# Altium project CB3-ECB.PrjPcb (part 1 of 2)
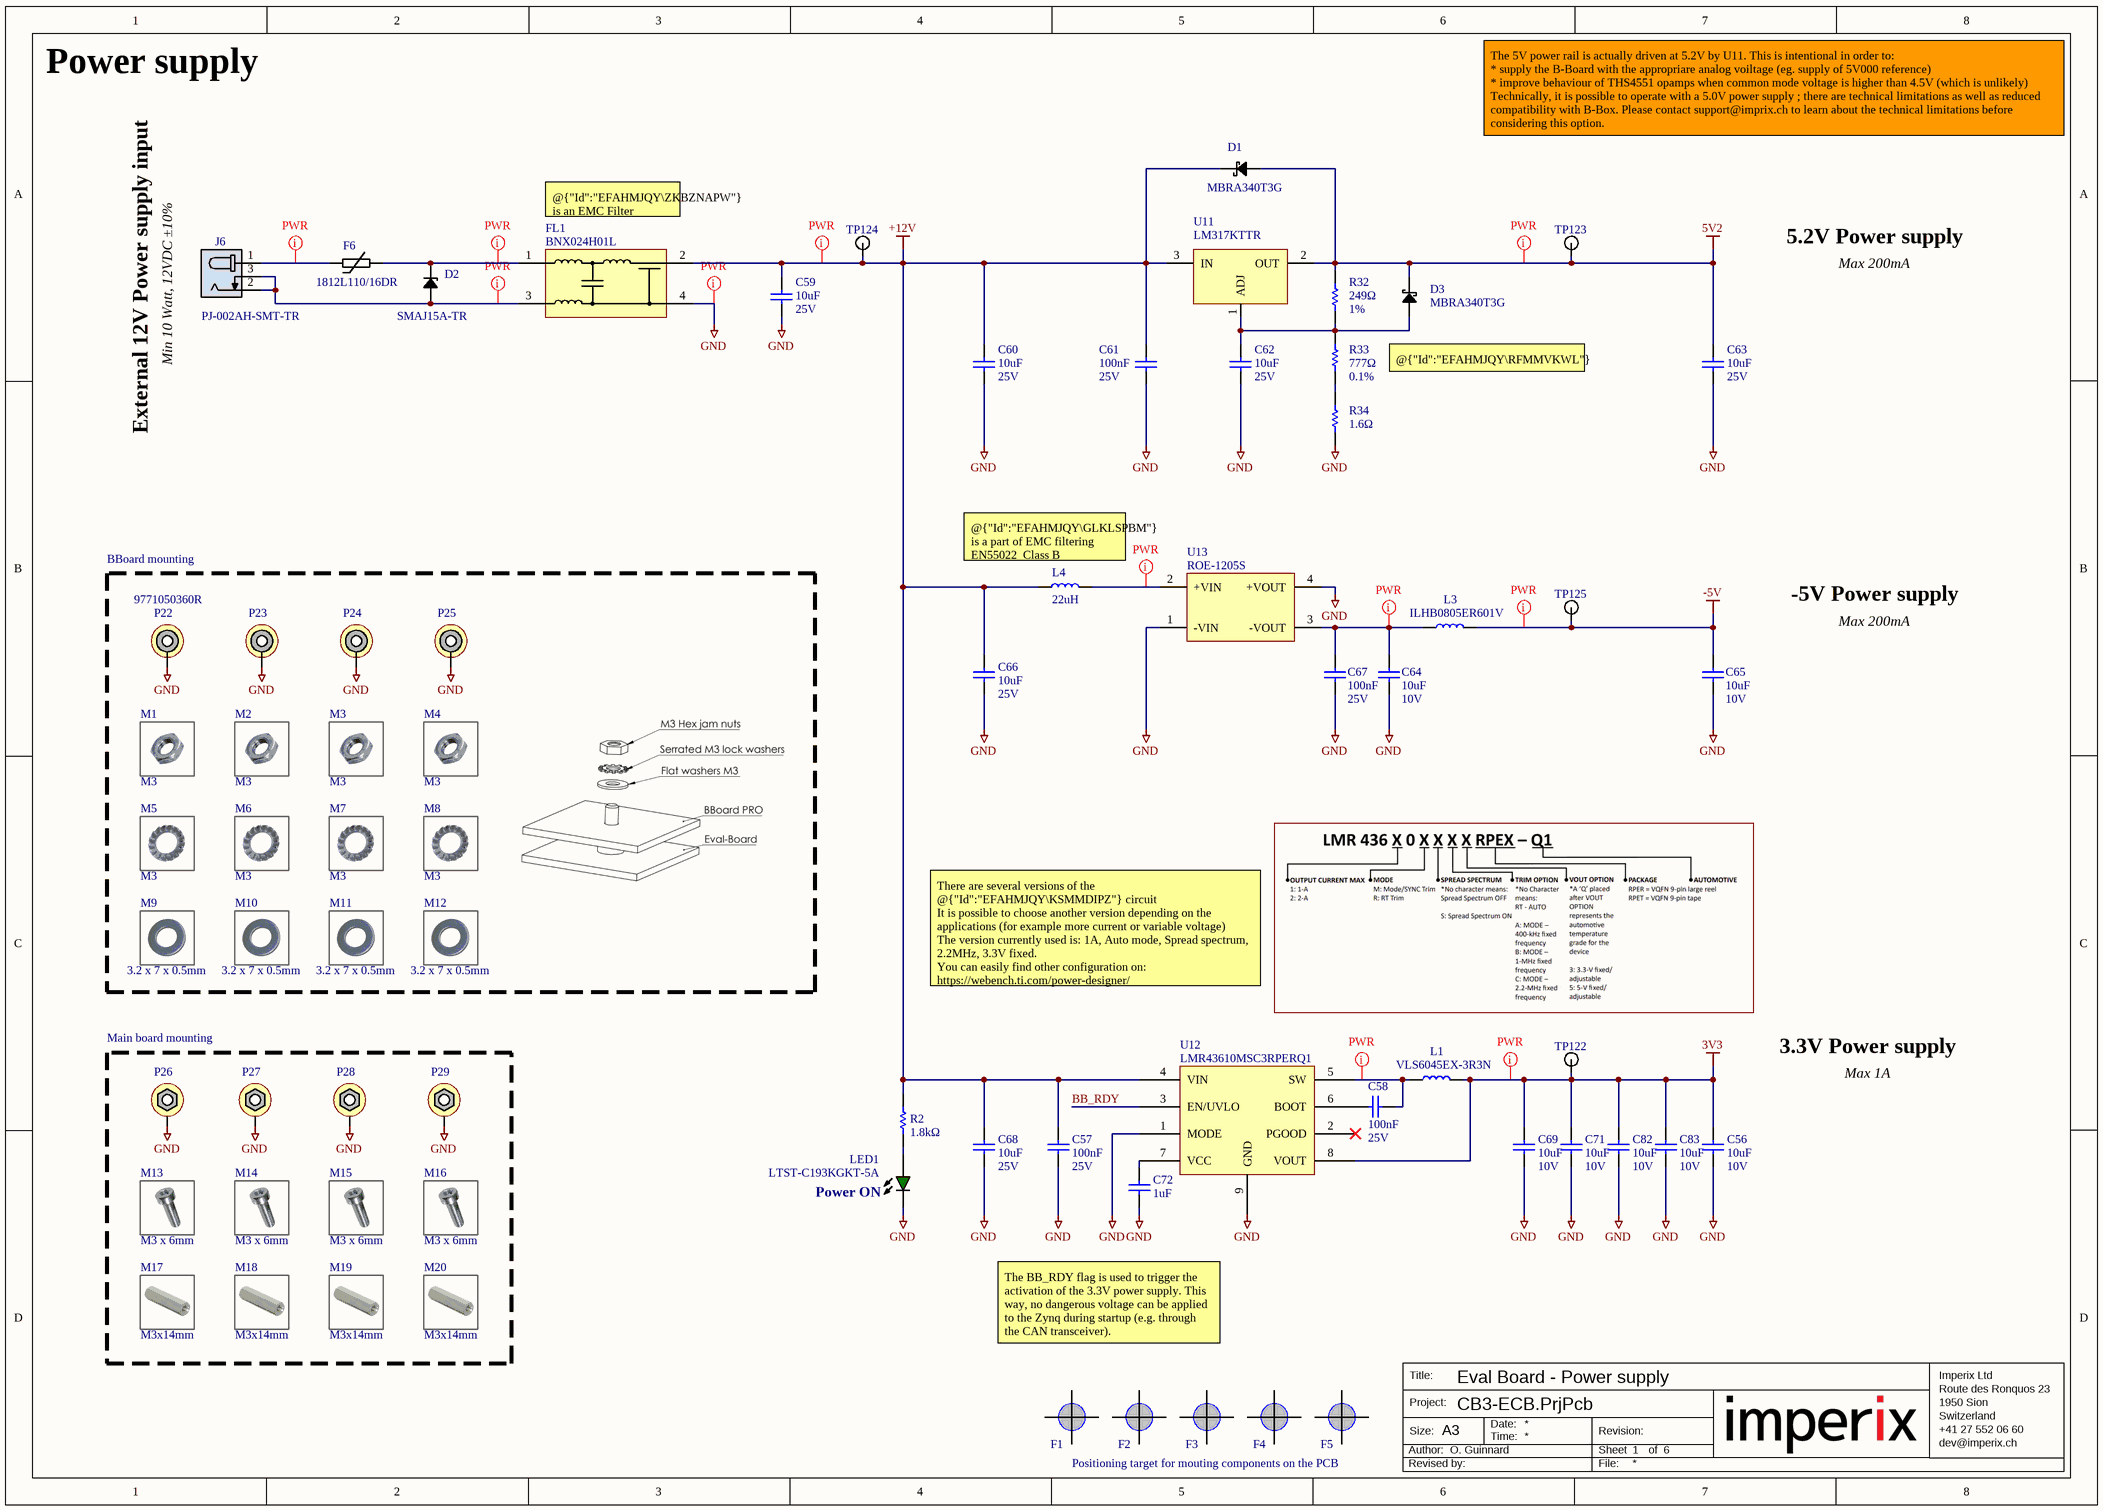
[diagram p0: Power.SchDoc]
ApprovedName: Nicolas Cherix; RevisionLetter: C; RevisionNumber: 1
6 sheets, 383 parts. Net scope: global (net labels, ports and power ports of the same name join across sheets).
Board files: CB3-ECB_PCB.PcbDoc, CB3_ECB_PCB_Pannelized.PcbDoc
Sheets:
  Power.SchDoc
  DAC.SchDoc
  ADC.SchDoc
  BBoard-JX1.SchDoc
  BBoard-JX2.SchDoc
  Test points.SchDoc

## Sheet Power.SchDoc: Eval Board - Power supply
size A3; ApprovedBy: Nicolas Cherix; Author: O. Guinnard; Organization: imperix Ltd; Address1: Rue de l'Industrie 10; Address2: 1950 Sion; Address3: Switzerland; Address4: +41 27 552 06 60; Revision: C1; SheetNumber: 1; SheetTotal: 6

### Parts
C56  value 10uF  Voltage Rating (DC): 10V  [CAPC1608L(0603)]  (hidden comment: CAP-10UF-10V-X5R-0603-10%)
C57  value 100nF  Voltage Rating (DC): 25V  [CAPC1005L(0402)]  (hidden comment: CAP-100NF-25V-X7R-0402-10%)
C58  value 100nF  Voltage Rating (DC): 25V  [CAPC1005L(0402)]  (hidden comment: CAP-100NF-25V-X7R-0402-10%)
C59  value 10uF  Voltage Rating (DC): 25V  [CAPC3216L(1206)]  (hidden comment: CAP-10UF-25V-X5R-1206-10%)
C60  value 10uF  Voltage Rating (DC): 25V  [CAPC3216L(1206)]  (hidden comment: CAP-10UF-25V-X5R-1206-10%)
C61  value 100nF  Voltage Rating (DC): 25V  [CAPC1005L(0402)]  (hidden comment: CAP-100NF-25V-X7R-0402-10%)
C62  value 10uF  Voltage Rating (DC): 25V  [CAPC3216L(1206)]  (hidden comment: CAP-10UF-25V-X5R-1206-10%)
C63  value 10uF  Voltage Rating (DC): 25V  [CAPC3216L(1206)]  (hidden comment: CAP-10UF-25V-X5R-1206-10%)
C64  value 10uF  Voltage Rating (DC): 10V  [CAPC1608L(0603)]  (hidden comment: CAP-10UF-10V-X5R-0603-10%)
C65  value 10uF  Voltage Rating (DC): 10V  [CAPC1608L(0603)]  (hidden comment: CAP-10UF-10V-X5R-0603-10%)
C66  value 10uF  Voltage Rating (DC): 25V  [CAPC3216L(1206)]  (hidden comment: CAP-10UF-25V-X5R-1206-10%)
C67  value 100nF  Voltage Rating (DC): 25V  [CAPC1005L(0402)]  (hidden comment: CAP-100NF-25V-X7R-0402-10%)
C68  value 10uF  Voltage Rating (DC): 25V  [CAPC3216L(1206)]  (hidden comment: CAP-10UF-25V-X5R-1206-10%)
C69  value 10uF  Voltage Rating (DC): 10V  [CAPC1608L(0603)]  (hidden comment: CAP-10UF-10V-X5R-0603-10%)
C71  value 10uF  Voltage Rating (DC): 10V  [CAPC1608L(0603)]  (hidden comment: CAP-10UF-10V-X5R-0603-10%)
C72  value 1uF  [CAPC1005L(0402)]  (hidden comment: CAP-1UF-6.3V-X5R-0402-5%)
C82  value 10uF  Voltage Rating (DC): 10V  [CAPC1608L(0603)]  (hidden comment: CAP-10UF-10V-X5R-0603-10%)
C83  value 10uF  Voltage Rating (DC): 10V  [CAPC1608L(0603)]  (hidden comment: CAP-10UF-10V-X5R-0603-10%)
D1  MBRA340T3G  [DO-214AC]
D2  SMAJ15A-TR  [DO-214AC]
D3  MBRA340T3G  [DO-214AC]
F1  Fiducial  [Fiducial050]  (value not drawn)  (no BOM)
F2  Fiducial  [Fiducial050]  (value not drawn)  (no BOM)
F3  Fiducial  [Fiducial050]  (value not drawn)  (no BOM)
F4  Fiducial  [Fiducial050]  (value not drawn)  (no BOM)
F5  Fiducial  [Fiducial050]  (value not drawn)  (no BOM)
F6  1812L110/16DR  [PTC Fuse(1812)]
FL1  BNX024H01L  [FP-BNX02-MFG]
J6  PJ-002AH-SMT-TR  [PJ-002AH-SMT-TR]
L1  VLS6045EX-3R3N  [VLS6045EX]
L3  ILHB0805ER601V  [RESC2012L(0805)]
L4  value 22uH  [Inductor 8400 Serie]  (hidden comment: 84223C)
LED1  LTST-C193KGKT-5A  [LED0603_GREEN]
M1  value M3  (hidden comment: 1090615)  (mechanical)
M2  value M3  (hidden comment: 1090615)  (mechanical)
M3  value M3  (hidden comment: 1090615)  (mechanical)
M4  value M3  (hidden comment: 1090615)  (mechanical)
M5  value M3  (hidden comment: 1278037)  (mechanical)
M6  value M3  (hidden comment: 1278037)  (mechanical)
M7  value M3  (hidden comment: 1278037)  (mechanical)
M8  value M3  (hidden comment: 1278037)  (mechanical)
M9  value 3.2 x 7 x 0.5mm  (hidden comment: 1887467)  (mechanical)
M10  value 3.2 x 7 x 0.5mm  (hidden comment: 1887467)  (mechanical)
M11  value 3.2 x 7 x 0.5mm  (hidden comment: 1887467)  (mechanical)
M12  value 3.2 x 7 x 0.5mm  (hidden comment: 1887467)  (mechanical)
M13  value M3 x 6mm  (hidden comment: 1145924)  (mechanical)
M14  value M3 x 6mm  (hidden comment: 1145924)  (mechanical)
M15  value M3 x 6mm  (hidden comment: 1145924)  (mechanical)
M16  value M3 x 6mm  (hidden comment: 1145924)  (mechanical)
M17  value M3x14mm  (hidden comment: 1382748)  (mechanical)
M18  value M3x14mm  (hidden comment: 1382748)  (mechanical)
M19  value M3x14mm  (hidden comment: 1382748)  (mechanical)
M20  value M3x14mm  (hidden comment: 1382748)  (mechanical)
P22  9771050360R  [9771050360R]
P23  9771050360R  [9771050360R]  (value not drawn)
P24  9771050360R  [9771050360R]  (value not drawn)
P25  9771050360R  [9771050360R]  (value not drawn)
P26  Spacer M3 connected  [Spacer M3 connected]  (value not drawn)  (no BOM)
P27  Spacer M3 connected  [Spacer M3 connected]  (value not drawn)  (no BOM)
P28  Spacer M3 connected  [Spacer M3 connected]  (value not drawn)  (no BOM)
P29  Spacer M3 connected  [Spacer M3 connected]  (value not drawn)  (no BOM)
R2  value 1.8kΩ  [RESC1608L(0603)]  (hidden comment: RES-1.8KΩ-1/8W-25PPM-0603-0.1%)
R32  value 249Ω  Tolerance: 1%  [RESC1005L(0402)]  (hidden comment: RES-249Ω-1/16W-100PPM-0402-1%)
R33  value 777Ω  Tolerance: 0.1%  [RESC1005L(0402)]  (hidden comment: RES-777Ω-1/16W-25PPM-0402-0.1%)
R34  value 1.6Ω  [RESC1005L(0402)]  (hidden comment: RES-1.6Ω-1/16WW-200PPM-0402-5%)
TP122  5001  [5001]  (value not drawn)
TP123  5001  [5001]  (value not drawn)
TP124  5001  [5001]  (value not drawn)
TP125  5001  [5001]  (value not drawn)
U11  LM317KTTR  [TO263-3]
U12  LMR43610MSC3RPERQ1  [LMR43610MSC3RPERQ1]
U13  ROE-1205S  [ROE]

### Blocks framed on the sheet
BBoard mounting: M1-M12 P22-P25
Main board mounting: M13-M20 P26-P29

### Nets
3V3: C56.2 C69.2 C71.2 C82.2 C83.2 L1.2 TP122.1(TP) U12.8(VOUT)
5V2: C63.2 D1.A D3.K R32.2 TP123.1(TP) U11.2(OUT)
+12V: C57.2 C59.2 C60.2 C61.2 C66.2 C68.2 D1.K FL1.2(CB) L4.1 R2.2 TP124.1(TP) U11.3(IN) U12.4(VIN)
-5V: C65.1 L3.2 TP125.1(TP)
GND: C56.1 C57.1 C59.1 C60.1 C61.1 C62.1 C63.1 C64.2 C65.2 C66.1 C67.2 C68.1 C69.1 C71.1 C72.1 C82.1 C83.1 FL1.4(CG) LED1.K P22.0 P23.0 P24.0 P25.0 P26.1 P27.1 P28.1 P29.1 R34.1 U12.1(MODE) U12.9(GND) U13.1(-VIN) U13.4(+VOUT)
BB_RDY: U12.3(EN/UVLO)
NetC58_1: C58.1 L1.1 U12.5(SW)
NetC58_2: C58.2 U12.6(BOOT)
NetC62_2: C62.2 D3.A R32.1 R33.2 U11.1(ADJ)
NetC64_1: C64.1 C67.1 L3.1 U13.3(-VOUT)
NetC72_2: C72.2 U12.7(VCC)
NetD2_A: D2.A FL1.3(PSG) J6.2 J6.3
NetD2_K: D2.K F6.2 FL1.1(B)
NetF6_1: F6.1 J6.1
NetL4_2: L4.2 U13.2(+VIN)
NetLED1_A: LED1.A R2.1
NetR33_1: R33.1 R34.2

Not connected (* = marked no-connect by the designer): U12 2(PGOOD)*

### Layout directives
net class PWR: 3V3, 5V2, +12V, -5V, GND, NetC58_1, NetC64_1, NetD2_A, NetD2_K, NetF6_1, NetL4_2

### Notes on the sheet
- Power supply
- The 5V power rail is actually driven at 5.2V by U11. This is intentional in order to:
  * supply the B-Board with the appropriare analog voiltage (eg. supply of 5V000 reference)
  * improve behaviour of THS4551 opamps when common mode voltage is higher than 4.5V (which is unlikely)
  Technically, it is possible to operate with a 5.0V power supply ; there are technical limitations as well as reduced compatibility with B-Box. Please contact support@imprix.ch to learn about the technical limitations before considering this option.
- (near FL1) @{"Id":"EFAHMJQY\ZKBZNAPW"} is an EMC Filter
- 5.2V Power supply
- External 12V Power supply input
- Min 10 Watt, 12VDC ±10%
- Max 200mA
- @{"Id":"EFAHMJQY\RFMMVKWL"} helps reduce the noise of @{"Id":"EFAHMJQY\SLPSMMLY"}
- (near L4) @{"Id":"EFAHMJQY\GLKLSPBM"} is a part of EMC filtering
  EN55022  Class B
- -5V Power supply
- There are several versions of the @{"Id":"EFAHMJQY\KSMMDIPZ"} circuit
  It is possible to choose another version depending on the applications (for example more current or variable voltage)
  The version currently used is: 1A, Auto mode, Spread spectrum, 2.2MHz, 3.3V fixed.
  You can easily find other configuration on: https://webench.ti.com/power-designer/
- 3.3V Power supply
- Max 1A
- (near LED1) Power ON
- The BB_RDY flag is used to trigger the activation of the 3.3V power supply. This way, no dangerous voltage can be applied to the Zynq during startup (e.g. through the CAN transceiver).
- Positioning target for mouting components on the PCB

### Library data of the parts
C56 C64 C65 C69 C71 C82 C83 = CMP-055-000003-7: CAP CER 10UF 10V X5R 0603 10% (Generic Imperix Component)
C57 C58 C61 C67 = CMP-004-000006-18: CAP CER 100NF 25V X7R 0402 10% (Generic Imperix Component)
C59 C60 C62 C63 C66 C68 = CMP-002-000022-5: CAP CER 10UF 25V X5R 1206 10% (Generic Imperix Component)
C72 = CMP-004-000008-13: CAP CER 1UF 6.3V X5R 0402 5% (Generic Imperix Component)
D1 D3 = CMP-005-000028-6: Diode Schottky 40 V 3A Surface Mount SMA; Max Forward Surge Current (Ifsm): 100A; Max Repetitive Reverse Voltage (Vrrm): 40V; Polarity: Standard; Element Configuration: Single; Forward Voltage: 450mV; Max Reverse Current: 300uA
D2 = CMP-030-000001-20: 32.5V Clamp 71A (8/20µs) Ipp Tvs Diode Surface Mount SMA (DO-214AC) Unidirectional; Voltage Rating (DC): 15V; Leakage Current: 200nA; Max Breakdown Voltage: 17.6V; Value: 975pF; Min Breakdown Voltage: 16.7V; Number of Elements: 1; Diode Type: ZENER; Power Line Protection: No; Power Dissipation: 400W; ESD Protection: Yes; Test Current: 1mA
F1-F5 = CMP-031-000000-13: Fiducial for pick&place (No BOM)
F6 = CMP-00170-3: PTC Resettable Fuse 1.1A(hold)  1.95A(trip) 16VDC 1812; Max Voltage Rating (DC): 16V; Approvals: cULus,TUV; Value: 180mR; Max Power Dissipation: 800mW; Max Current Rating: 100A; Time to Trip: 300ms
FL1 = CMP-00068-6: EMI Filter Block 15A 50VDC Flat Style SMD Automotive Embossed T/R
J6 = CMP-056-000006-11: 2.0 x 6.5 mm, 5.0 A, Horizontal, Surface Mount (SMT), Dc Power Jack Connector; Body Color: Black; Gender: Male; Shielding: Unshielded
L1 = CMP-259-000003-2: Inductor Power Shielded Wirewound 3.3uH 30% 100KHz Ferrite 4.95A 0.0299Ohm DCR 2424 T/R; DC Resistance (DCR): 30mR; Saturation Current: 6.5A
L3 = CMP-007-000004-5: Ferrite Beads Multi-Layer High Current 600Ohm 25% 100MHz 2A 100mOhm DCR 0805 T/R; DC Resistance (DCR): 100mR; Impedance: 600R; Number of Lines: 1; Shielding: Shielded; Value: 600Ω 2A
L4 = CMP-00092-4: Inductor Power Wirewound 22uH 10% 0.6A 0.6Ohm DCR 1812; Shielding: Unshielded; DC Resistance (DCR): 600mR; Max DC Current: 600mA
LED1 = CMP-030-000000-10: LED GREEN CLEAR 0603 SMD; Lens Size: 0.8mm; Lens Color: Colorless; Illumination Color: Green,Yellow; Dominant Wavelength: 576.5nm; Test Current: 5mA; Luminous Intensity: 28mcd; Power Dissipation: 75mW; Lens Style: Flat,Diffused,Colorless,Rectangular,Clear; Forward Voltage: 2.3V; Reverse Voltage: 5V; Viewing Angle: 130°; Number of Elements: 1; Forward Current: 30mA
M1-M4 = CMP-00174-1: M3 Hex jam nuts
M5-M8 = CMP-00031-5: Serrated M3 lock washers type A, external serrations
M9-M12 = CMP-00030-4: Flat washers M3 without chamfer
M13-M16 = CMP-00026-4: Hexalobular (6 Lobe) socket head cap M3x6mm screws with low head, fully threaded; Thread size: M3
M17-M20 = CMP-00173-1: Brass Spacer M3x14mm  Metric Thread int./int.; Plating: Nickel; Gender: Female, Female; Threaded/Unthreaded: Threaded
P22-P25 = CMP-002-000068-13: WA-SMSE SMT Steel Spacer, M3x5mm Thread External; Thread Size: M3; Threaded/Unthreaded: Threaded; Outside Diameter: 0.236inch; Plating: Tin; Body Length: 5mm
P26-P29 = CMP-00128-10: Hole and pad for spacer M3; Outside diameter SW: 5.5mm
R2 = CMP-00098-1: RES SMD 1.8KΩ 1/8W 25PPM 0603 0.1% (Generic Imperix Component); Temperature Coefficient: 25ppm/°C
R32 = CMP-132-000003-2: RES SMD 249Ω 1/16W 100PPM 0402 1% (Generic Imperix Component); Temperature Coefficient: 100ppm/°C
R33 = CMP-150-000004-2: RES SMD 777Ω 1/16W 25PPM 0402 0.1% (Generic Imperix Component); Temperature Coefficient: 25ppm/°C
R34 = CMP-004-000018-3: RES SMD 1.6Ω 1/16WW 200PPM 0402 5% (Generic Imperix Component); Temperature Coefficient: 200ppm/°C; Power Rating: 1/16W
TP122-TP125 = CMP-049-000000-14: Black PC Test Point, Miniature Phosphor Bronze Silver Plating Through Hole Mounting Type; Inside Diameter: 1.27mm; Hole Diameter: 1.6mm; Outside Diameter: 2.54mm; Number of Contacts: 1; Insulation: Insulated
U11 = CMP-011-000003-10: IC REG LINEAR ADJ 1.5A DDPAK; Number of Regulators: 1; Dropout Voltage: 2V; Polarity: Positive; Output Type: Adjustable; Quiescent Current: 3.5mA; Max Supply Voltage: 40V; Power Supply Rejection Ratio (PSRR): 64dB; Min Output Voltage: 1.25V; Reference Voltage: 1.3V; Output Voltage: 37V; Min Input Voltage: 4.2V
U12 = CMP-00162-5: LMR436x0, 36-V, 1-A Buck Converter
U13 = CMP-004-000025-11: Isolated Module DC DC Converter 1 Output 5V 200mA 10.8V - 13.2V Input; Isolation Voltage: 1kV; Efficiency: 80%; Number of Outputs: 1; Max Power Dissipation: 1W

## Sheet DAC.SchDoc: Eval Board -  Analog outputs
size A3; ApprovedBy: Nicolas Cherix; Author: O. Guinnard; Organization: imperix Ltd; Address1: Rue de l'Industrie 10; Address2: 1950 Sion; Address3: Switzerland; Address4: +41 27 552 06 60; Revision: C1; SheetNumber: 2; SheetTotal: 6
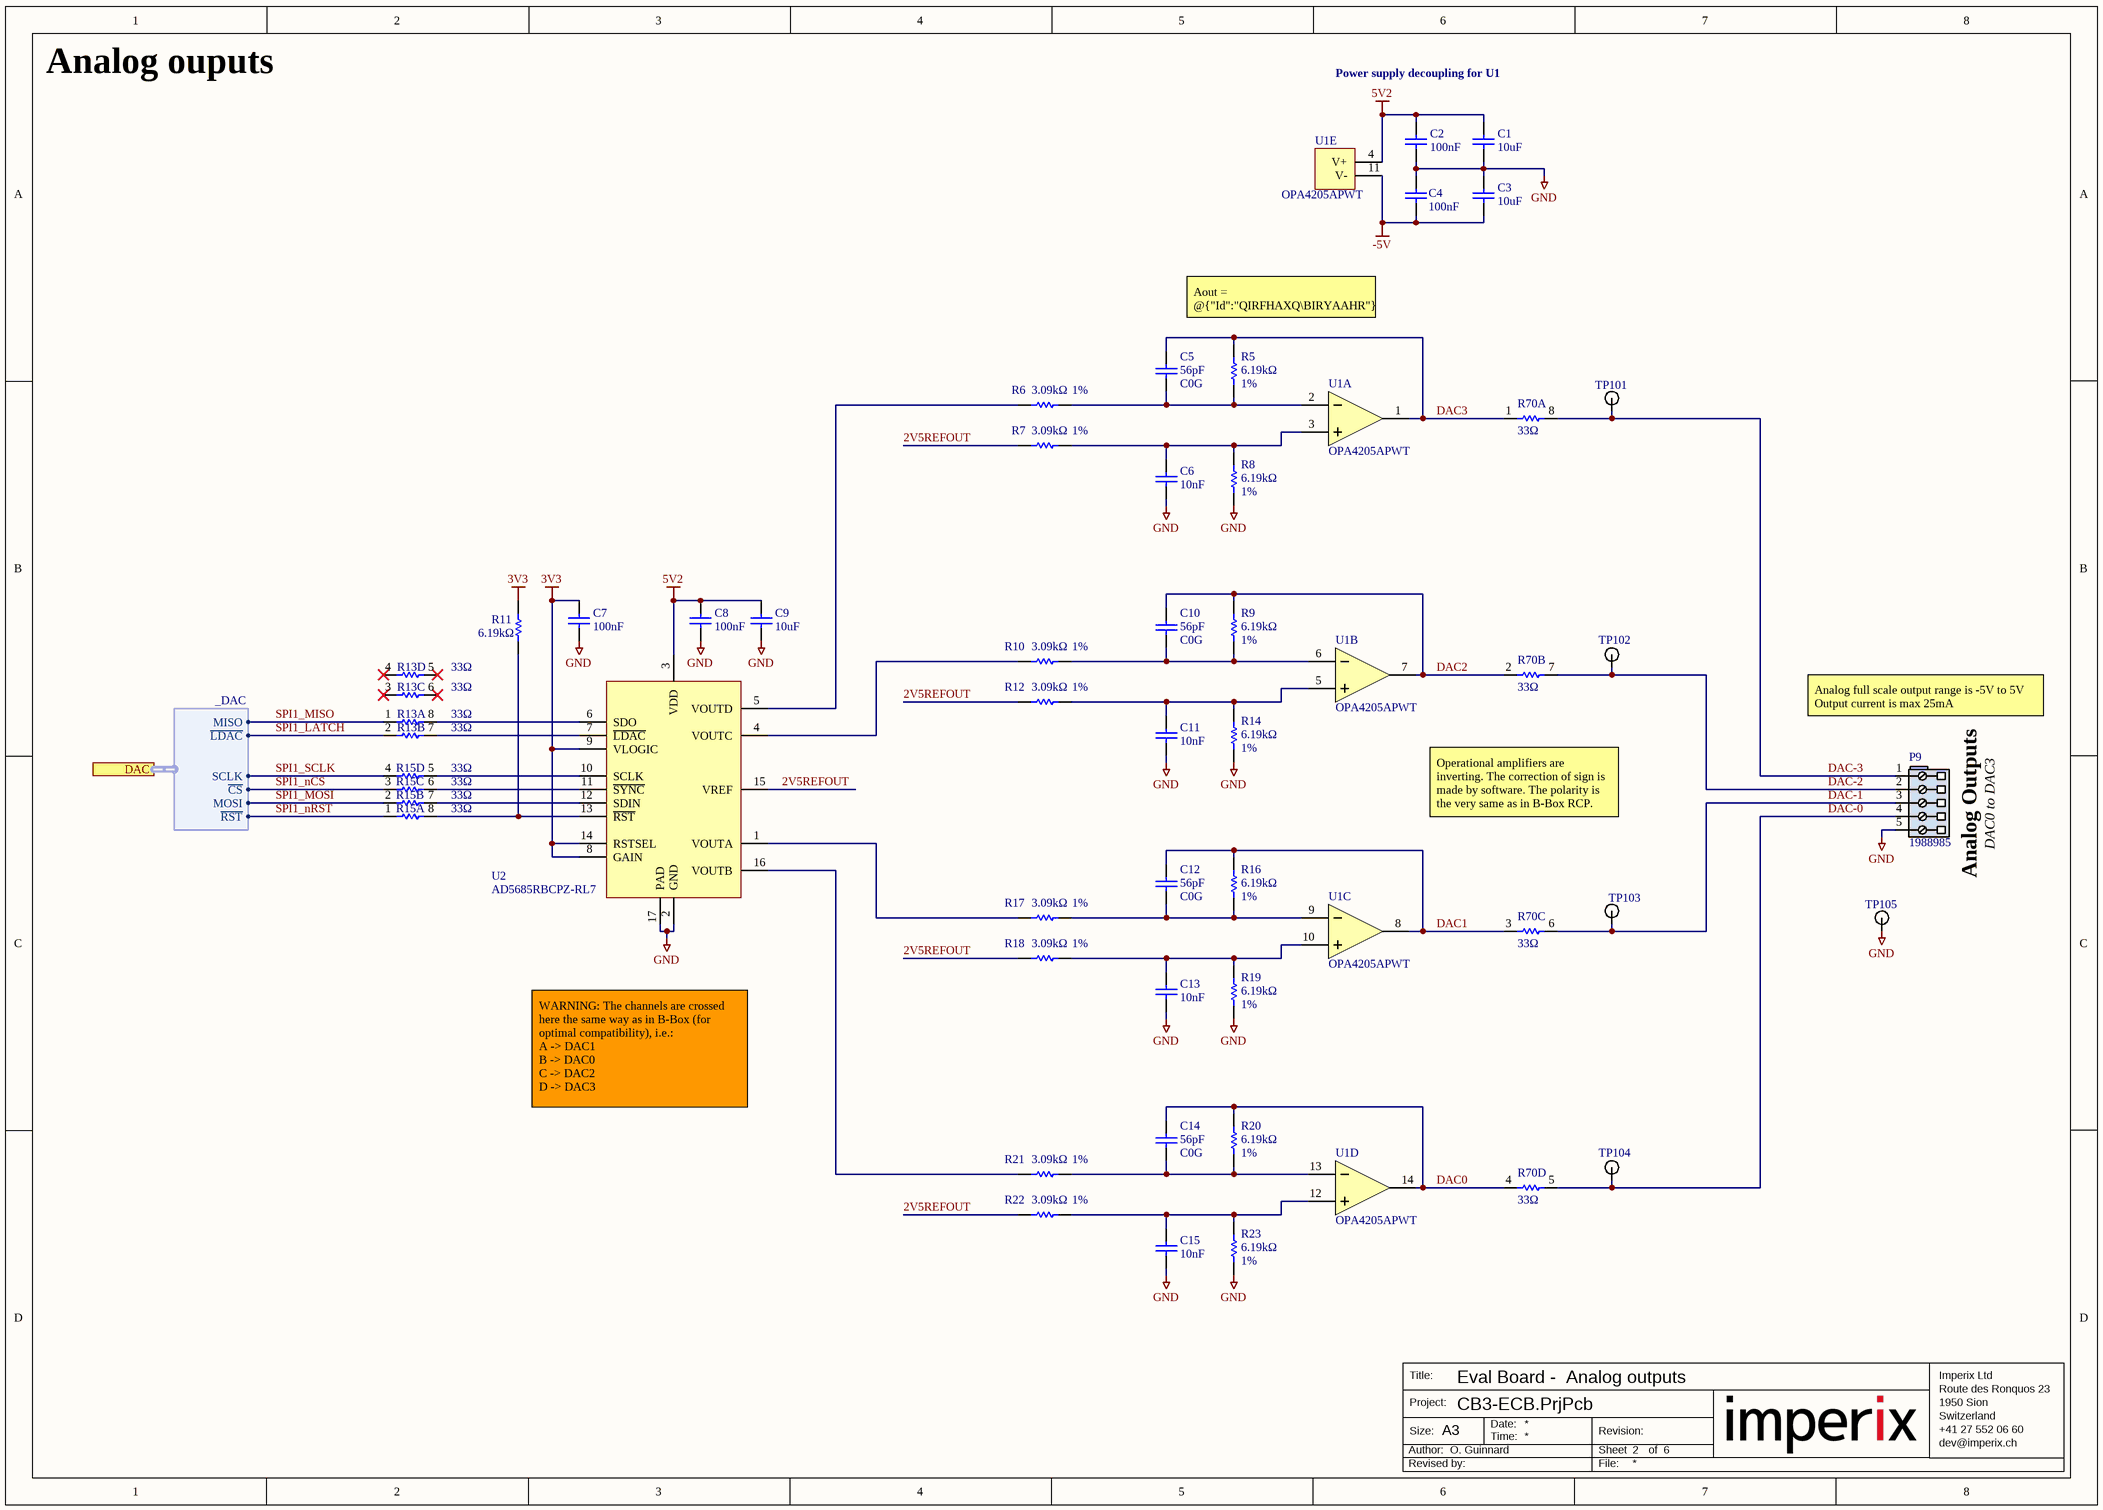
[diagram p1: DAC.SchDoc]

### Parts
C1  value 10uF  [CAPC1608L(0603)]  (hidden comment: CAP-10UF-10V-X5R-0603-10%)
C2  value 100nF  [CAPC1005L(0402)]  (hidden comment: CAP-100NF-25V-X7R-0402-10%)
C3  value 10uF  [CAPC1608L(0603)]  (hidden comment: CAP-10UF-10V-X5R-0603-10%)
C4  value 100nF  [CAPC1005L(0402)]  (hidden comment: CAP-100NF-25V-X7R-0402-10%)
C5  value 56pF  Dielectric: C0G  [CAPC1005L(0402)]  (hidden comment: CAP-56PF-50V-C0G-0402-1%)
C6  value 10nF  [CAPC1005L(0402)]  (hidden comment: CAP-10NF-25V-X7R-0402-10%)
C7  value 100nF  [CAPC1005L(0402)]  (hidden comment: CAP-100NF-25V-X7R-0402-10%)
C8  value 100nF  [CAPC1005L(0402)]  (hidden comment: CAP-100NF-25V-X7R-0402-10%)
C9  value 10uF  [CAPC1608L(0603)]  (hidden comment: CAP-10UF-10V-X5R-0603-10%)
C10  value 56pF  Dielectric: C0G  [CAPC1005L(0402)]  (hidden comment: CAP-56PF-50V-C0G-0402-1%)
C11  value 10nF  [CAPC1005L(0402)]  (hidden comment: CAP-10NF-25V-X7R-0402-10%)
C12  value 56pF  Dielectric: C0G  [CAPC1005L(0402)]  (hidden comment: CAP-56PF-50V-C0G-0402-1%)
C13  value 10nF  [CAPC1005L(0402)]  (hidden comment: CAP-10NF-25V-X7R-0402-10%)
C14  value 56pF  Dielectric: C0G  [CAPC1005L(0402)]  (hidden comment: CAP-56PF-50V-C0G-0402-1%)
C15  value 10nF  [CAPC1005L(0402)]  (hidden comment: CAP-10NF-25V-X7R-0402-10%)
P9  1988985  [1988985]
R5  value 6.19kΩ  Tolerance: 1%  [RESC1005L(0402)]  (hidden comment: RES-6.19KΩ-1/16W-100PPM-0402-1%)
R6  value 3.09kΩ  Tolerance: 1%  [RESC1005L(0402)]  (hidden comment: RES-3.09KΩ-1/16W-100PPM-0402-1%)
R7  value 3.09kΩ  Tolerance: 1%  [RESC1005L(0402)]  (hidden comment: RES-3.09KΩ-1/16W-100PPM-0402-1%)
R8  value 6.19kΩ  Tolerance: 1%  [RESC1005L(0402)]  (hidden comment: RES-6.19KΩ-1/16W-100PPM-0402-1%)
R9  value 6.19kΩ  Tolerance: 1%  [RESC1005L(0402)]  (hidden comment: RES-6.19KΩ-1/16W-100PPM-0402-1%)
R10  value 3.09kΩ  Tolerance: 1%  [RESC1005L(0402)]  (hidden comment: RES-3.09KΩ-1/16W-100PPM-0402-1%)
R11  value 6.19kΩ  [RESC1005L(0402)]  (hidden comment: RES-6.19KΩ-1/16W-100PPM-0402-1%)
R12  value 3.09kΩ  Tolerance: 1%  [RESC1005L(0402)]  (hidden comment: RES-3.09KΩ-1/16W-100PPM-0402-1%)
R13  value 33Ω  [RESQUAD0804]  (hidden comment: EXB-28V330JX)  (parts A,B,C,D of 4)
R14  value 6.19kΩ  Tolerance: 1%  [RESC1005L(0402)]  (hidden comment: RES-6.19KΩ-1/16W-100PPM-0402-1%)
R15  value 33Ω  [RESQUAD0804]  (hidden comment: EXB-28V330JX)  (parts A,B,C,D of 4)
R16  value 6.19kΩ  Tolerance: 1%  [RESC1005L(0402)]  (hidden comment: RES-6.19KΩ-1/16W-100PPM-0402-1%)
R17  value 3.09kΩ  Tolerance: 1%  [RESC1005L(0402)]  (hidden comment: RES-3.09KΩ-1/16W-100PPM-0402-1%)
R18  value 3.09kΩ  Tolerance: 1%  [RESC1005L(0402)]  (hidden comment: RES-3.09KΩ-1/16W-100PPM-0402-1%)
R19  value 6.19kΩ  Tolerance: 1%  [RESC1005L(0402)]  (hidden comment: RES-6.19KΩ-1/16W-100PPM-0402-1%)
R20  value 6.19kΩ  Tolerance: 1%  [RESC1005L(0402)]  (hidden comment: RES-6.19KΩ-1/16W-100PPM-0402-1%)
R21  value 3.09kΩ  Tolerance: 1%  [RESC1005L(0402)]  (hidden comment: RES-3.09KΩ-1/16W-100PPM-0402-1%)
R22  value 3.09kΩ  Tolerance: 1%  [RESC1005L(0402)]  (hidden comment: RES-3.09KΩ-1/16W-100PPM-0402-1%)
R23  value 6.19kΩ  Tolerance: 1%  [RESC1005L(0402)]  (hidden comment: RES-6.19KΩ-1/16W-100PPM-0402-1%)
R70  value 33Ω  [RESQUAD0804]  (hidden comment: EXB-28V330JX)  (parts A,B,C,D of 4)
TP101  5001  [5001]  (value not drawn)
TP102  5001  [5001]  (value not drawn)
TP103  5001  [5001]  (value not drawn)
TP104  5001  [5001]  (value not drawn)
TP105  5001  [5001]  (value not drawn)
U1  OPA4205APWT  [TSSOP65P640-14N]  (parts A,B,C,D,E of 5)
U2  AD5685RBCPZ-RL7  [QFN50P300X300-16WAL]

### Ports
DAC (harness _DAC)

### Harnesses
_DAC: MOSI, MISO, SCLK, ~{CS}, ~{LDAC}, ~{RST}

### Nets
3V3: C7.2 R11.2 U2.8(GAIN) U2.9(VLOGIC) U2.14(RSTSEL)
5V2: C1.2 C2.2 C8.2 C9.2 U1.4(V+) U2.3(VDD)
-5V: C3.1 C4.1 U1.11(V-)
GND: C1.1 C2.1 C3.2 C4.2 C6.1 C7.1 C8.1 C9.1 C11.1 C13.1 C15.1 P9.5 R8.1 R14.1 R19.1 R23.1 TP105.1(TP) U2.2(GND) U2.17(PAD)
2V5REFOUT: R7.2 R12.2 R18.2 R22.2 U2.15(VREF)
DAC0: C14.2 R20.2 R70.4 U1.14(OUT)
DAC1: C12.2 R16.2 R70.3 U1.8(OUT)
DAC2: C10.2 R9.2 R70.2 U1.7(OUT)
DAC3: C5.2 R5.2 R70.1 U1.1(OUT)
DAC-0: P9.4 R70.5 TP104.1(TP)
DAC-1: P9.3 R70.6 TP103.1(TP)
DAC-2: P9.2 R70.7 TP102.1(TP)
DAC-3: P9.1 R70.8 TP101.1(TP)
SPI1_LATCH: R13.2 ; port DAC.~{LDAC}
SPI1_MISO: R13.1 ; port DAC.MISO
SPI1_MOSI: R15.2 ; port DAC.MOSI
SPI1_nCS: R15.3 ; port DAC.~{CS}
SPI1_nRST: R15.1 ; port DAC.~{RST}
SPI1_SCLK: R15.4 ; port DAC.SCLK
NetC5_1: C5.1 R5.1 R6.1 U1.2(IN-)
NetC6_2: C6.2 R7.1 R8.2 U1.3(IN+)
NetC10_1: C10.1 R9.1 R10.1 U1.6(IN-)
NetC11_2: C11.2 R12.1 R14.2 U1.5(IN+)
NetC12_1: C12.1 R16.1 R17.1 U1.9(IN-)
NetC13_2: C13.2 R18.1 R19.2 U1.10(IN+)
NetC14_1: C14.1 R20.1 R21.1 U1.13(IN-)
NetC15_2: C15.2 R22.1 R23.2 U1.12(IN+)
NetR6_2: R6.2 U2.5(VOUTD)
NetR10_2: R10.2 U2.4(VOUTC)
NetR11_1: R11.1 R15.8 U2.13(~{RST})
NetR13_7: R13.7 U2.7(~{LDAC})
NetR13_8: R13.8 U2.6(SDO)
NetR15_5: R15.5 U2.10(SCLK)
NetR15_6: R15.6 U2.11(~{SYNC})
NetR15_7: R15.7 U2.12(SDIN)
NetR17_2: R17.2 U2.1(VOUTA)
NetR21_2: R21.2 U2.16(VOUTB)

Not connected (* = marked no-connect by the designer): R13 3* 4* 5* 6*

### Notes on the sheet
- Analog ouputs
- Power supply decoupling for U1
- Aout = @{"Id":"QIRFHAXQ\BIRYAAHR"} / @{"Id":"QIRFHAXQ\GPNTABEF"} *(Vref-Vin)
  = 2*(Vref-Vin)
- Analog full scale output range is -5V to 5V
  Output current is max 25mA
- Operational amplifiers are inverting. The correction of sign is made by software. The polarity is the very same as in B-Box RCP.
- (near P9) Analog Outputs
- DAC0 to DAC3
- WARNING: The channels are crossed here the same way as in B-Box (for optimal compatibility), i.e.:
  A -> DAC1
  B -> DAC0
  C -> DAC2
  D -> DAC3

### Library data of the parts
C1 C3 C9 = CMP-055-000003-7: as C56 on sheet Power
C2 C4 C7 C8 = CMP-004-000006-18: as C57 on sheet Power
C5 C10 C12 C14 = CMP-027-000004-13: CAP CER 56PF 50V C0G 0402 1% (Generic Imperix Component)
C6 C11 C13 C15 = CMP-012-000001-12: CAP CER 10NF 25V X7R 0402 10% (Generic Imperix Component)
P9 = CMP-003-000046-13: Conn PC Terminal Block 5 POS 3.5mm Solder Thru-Hole 17.5A; Number of Poles: 5; Voltage: 300V; Current: 10A; Approvals: UL,EAC; Number of Levels: 1; Wire Gauge (Max): 26AWG; Gender: Male; Wire Gauge (Min): 16AWG; Voltage Rating: 160V
R5 R8 R9 R11 R14 R16 R19 R20 R23 = CMP-009-000034-6: RES SMD 6.19KΩ 1/16W 100PPM 0402 1% (Generic Imperix Component); Temperature Coefficient: 100ppm/°C
R6 R7 R10 R12 R17 R18 R21 R22 = CMP-00012-1: RES SMD 3.09KΩ 1/16W 100PPM 0402 1% (Generic Imperix Component); Temperature Coefficient: 100ppm/°C
R13 R15 R70 = CMP-009-000035-3: Res Thick Film Array 33 Ohm 5% ±200ppm/°C ISOL 8-Pin 0804(4 X 0402) Convex SMD Automotive T/R; Power Rating: 62.5mW; Voltage Rating (DC): 100V; Circuit Type: Isolated; Power Dissipation: 63mW; Number of Elements: 4; Number of Contacts: 8; Voltage Rating: 50V
TP101-TP105 = CMP-049-000000-14: Black PC Test Point, Miniature Phosphor Bronze Silver Plating Through Hole Mounting Type; Hole Diameter: 1.6mm; Inside Diameter: 1.27mm; Outside Diameter: 2.54mm; Number of Contacts: 1; Insulation: Insulated
U1 = CMP-00166-1: Precision Amplifiers Low-power low-noise four-channel precision amplifier with e-trim and super-beta inputs; Number of Channels: 4; Operating Supply Current: 0.24mA; Gain Bandwidth Product: 3.6MHz; Input Offset Voltage (Vos): 2uV; Input Bias Current: 100pA; Slew Rate: 4V/µs
U2 = CMP-029-000000-12: DAC 4-CH Resistor-String 14-bit 16-Pin LFCSP EP T/R; Supply Type: Analog,Digital; Settling Time: 5us; Number of Converters: 4; Min Output Voltage: 2.7V; Min Input Voltage: 750mV; Sampling Rate: 25MS/s; Signal to Noise Ratio (SNR): 90dB; Power Dissipation: 7.15mW; Output Type: Voltage; Differential Output: No; Max Output Voltage: 5.5V; Supply Current: 1.1mA; Output Polarity: Unipolar; Integral Nonlinearity (INL): 1LSB; Interface: SPI,Serial; Resolution: 14b; Number of Bits: 14; Slew Rate: 0.8V/µs

## Sheet ADC.SchDoc: Eval Board -  Analog differential inputs
size A3; ApprovedBy: Nicolas Cherix; Author: O. Guinnard; Organization: imperix Ltd; Address1: Rue de l'Industrie 10; Address2: 1950 Sion; Address3: Switzerland; Address4: +41 27 552 06 60; Revision: C1; SheetNumber: 3; SheetTotal: 6
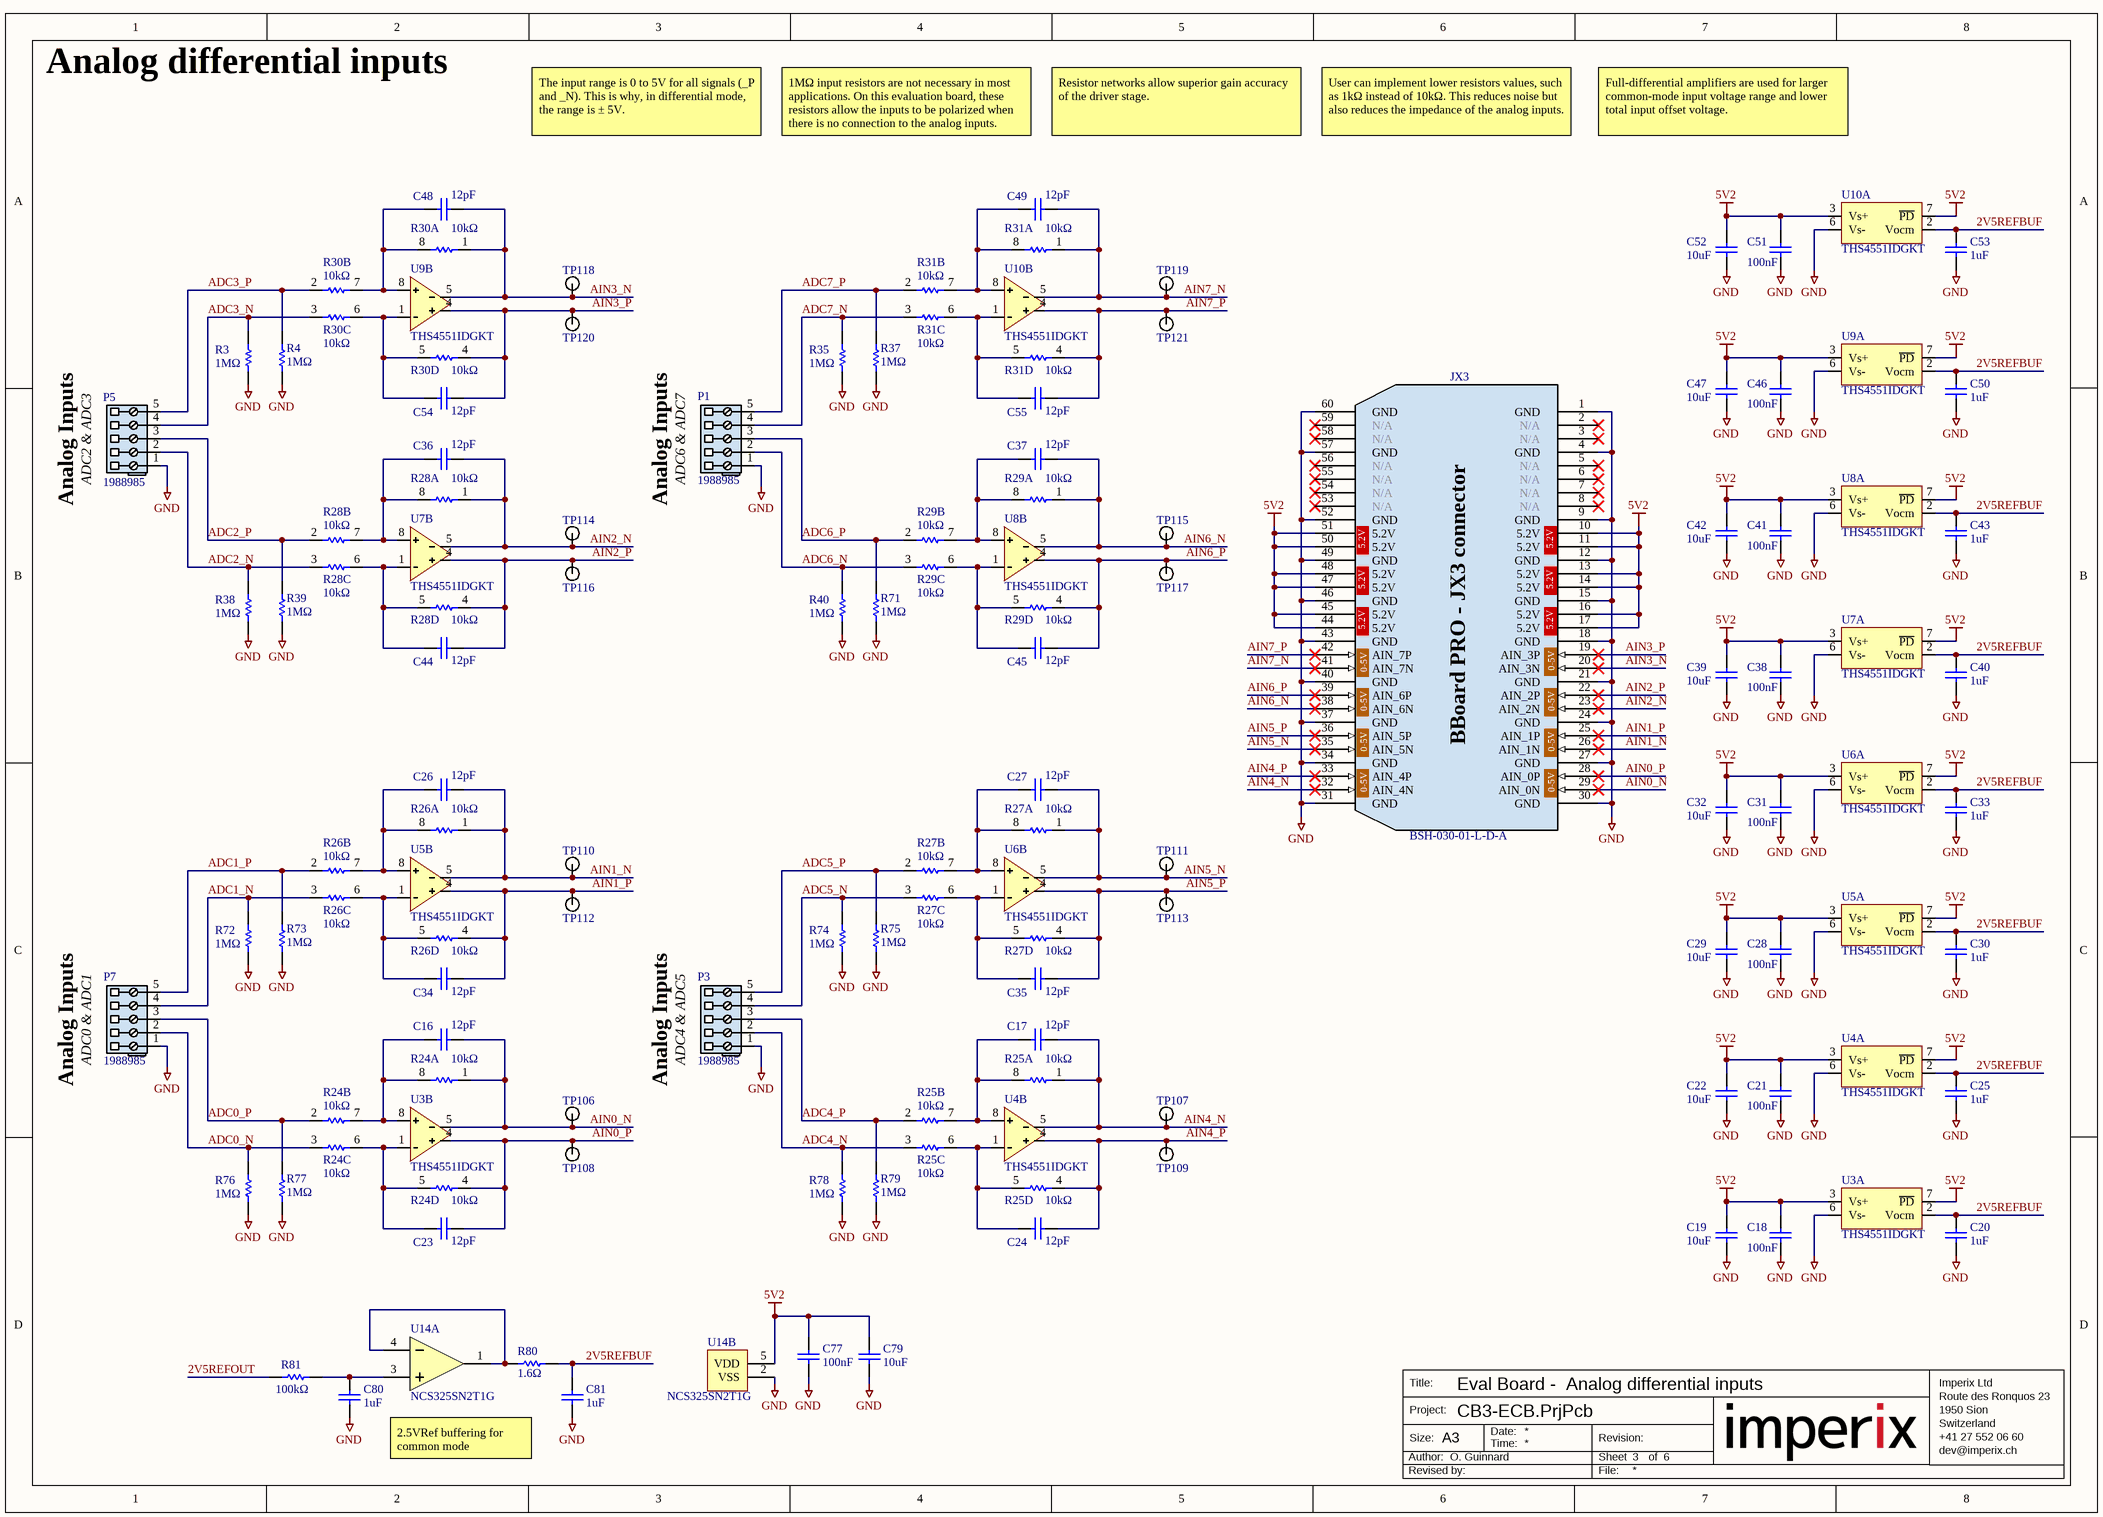
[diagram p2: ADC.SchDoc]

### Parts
C16  value 12pF  [CAPC1005L(0402)]  (hidden comment: CAP-12PF-50V-C0G-0402-5%)
C17  value 12pF  [CAPC1005L(0402)]  (hidden comment: CAP-12PF-50V-C0G-0402-5%)
C18  value 100nF  [CAPC1005L(0402)]  (hidden comment: CAP-100NF-25V-X7R-0402-10%)
C19  value 10uF  [CAPC1608L(0603)]  (hidden comment: CAP-10UF-10V-X5R-0603-10%)
C20  value 1uF  [CAPC1005L(0402)]  (hidden comment: CAP-1UF-6.3V-X5R-0402-5%)
C21  value 100nF  [CAPC1005L(0402)]  (hidden comment: CAP-100NF-25V-X7R-0402-10%)
C22  value 10uF  [CAPC1608L(0603)]  (hidden comment: CAP-10UF-10V-X5R-0603-10%)
C23  value 12pF  [CAPC1005L(0402)]  (hidden comment: CAP-12PF-50V-C0G-0402-5%)
C24  value 12pF  [CAPC1005L(0402)]  (hidden comment: CAP-12PF-50V-C0G-0402-5%)
C25  value 1uF  [CAPC1005L(0402)]  (hidden comment: CAP-1UF-6.3V-X5R-0402-5%)
C26  value 12pF  [CAPC1005L(0402)]  (hidden comment: CAP-12PF-50V-C0G-0402-5%)
C27  value 12pF  [CAPC1005L(0402)]  (hidden comment: CAP-12PF-50V-C0G-0402-5%)
C28  value 100nF  [CAPC1005L(0402)]  (hidden comment: CAP-100NF-25V-X7R-0402-10%)
C29  value 10uF  [CAPC1608L(0603)]  (hidden comment: CAP-10UF-10V-X5R-0603-10%)
C30  value 1uF  [CAPC1005L(0402)]  (hidden comment: CAP-1UF-6.3V-X5R-0402-5%)
C31  value 100nF  [CAPC1005L(0402)]  (hidden comment: CAP-100NF-25V-X7R-0402-10%)
C32  value 10uF  [CAPC1608L(0603)]  (hidden comment: CAP-10UF-10V-X5R-0603-10%)
C33  value 1uF  [CAPC1005L(0402)]  (hidden comment: CAP-1UF-6.3V-X5R-0402-5%)
C34  value 12pF  [CAPC1005L(0402)]  (hidden comment: CAP-12PF-50V-C0G-0402-5%)
C35  value 12pF  [CAPC1005L(0402)]  (hidden comment: CAP-12PF-50V-C0G-0402-5%)
C36  value 12pF  [CAPC1005L(0402)]  (hidden comment: CAP-12PF-50V-C0G-0402-5%)
C37  value 12pF  [CAPC1005L(0402)]  (hidden comment: CAP-12PF-50V-C0G-0402-5%)
C38  value 100nF  [CAPC1005L(0402)]  (hidden comment: CAP-100NF-25V-X7R-0402-10%)
C39  value 10uF  [CAPC1608L(0603)]  (hidden comment: CAP-10UF-10V-X5R-0603-10%)
C40  value 1uF  [CAPC1005L(0402)]  (hidden comment: CAP-1UF-6.3V-X5R-0402-5%)
C41  value 100nF  [CAPC1005L(0402)]  (hidden comment: CAP-100NF-25V-X7R-0402-10%)
C42  value 10uF  [CAPC1608L(0603)]  (hidden comment: CAP-10UF-10V-X5R-0603-10%)
C43  value 1uF  [CAPC1005L(0402)]  (hidden comment: CAP-1UF-6.3V-X5R-0402-5%)
C44  value 12pF  [CAPC1005L(0402)]  (hidden comment: CAP-12PF-50V-C0G-0402-5%)
C45  value 12pF  [CAPC1005L(0402)]  (hidden comment: CAP-12PF-50V-C0G-0402-5%)
C46  value 100nF  [CAPC1005L(0402)]  (hidden comment: CAP-100NF-25V-X7R-0402-10%)
C47  value 10uF  [CAPC1608L(0603)]  (hidden comment: CAP-10UF-10V-X5R-0603-10%)
C48  value 12pF  [CAPC1005L(0402)]  (hidden comment: CAP-12PF-50V-C0G-0402-5%)
C49  value 12pF  [CAPC1005L(0402)]  (hidden comment: CAP-12PF-50V-C0G-0402-5%)
C50  value 1uF  [CAPC1005L(0402)]  (hidden comment: CAP-1UF-6.3V-X5R-0402-5%)
C51  value 100nF  [CAPC1005L(0402)]  (hidden comment: CAP-100NF-25V-X7R-0402-10%)
C52  value 10uF  [CAPC1608L(0603)]  (hidden comment: CAP-10UF-10V-X5R-0603-10%)
C53  value 1uF  [CAPC1005L(0402)]  (hidden comment: CAP-1UF-6.3V-X5R-0402-5%)
C54  value 12pF  [CAPC1005L(0402)]  (hidden comment: CAP-12PF-50V-C0G-0402-5%)
C55  value 12pF  [CAPC1005L(0402)]  (hidden comment: CAP-12PF-50V-C0G-0402-5%)
C77  value 100nF  [CAPC1005L(0402)]  (hidden comment: CAP-100NF-25V-X7R-0402-10%)
C79  value 10uF  [CAPC1608L(0603)]  (hidden comment: CAP-10UF-10V-X5R-0603-10%)
C80  value 1uF  [CAPC1005L(0402)]  (hidden comment: CAP-1UF-6.3V-X5R-0402-5%)
C81  value 1uF  [CAPC1005L(0402)]  (hidden comment: CAP-1UF-6.3V-X5R-0402-5%)
JX3  BSH-030-01-L-D-A  [BSH-030-01-L-D-A]
P1  1988985  [1988985]
P3  1988985  [1988985]
P5  1988985  [1988985]
P7  1988985  [1988985]
R3  value 1MΩ  [RESC1005L(0402)]  (hidden comment: RES-1MΩ-1/16W-100PPM-0402-1%)
R4  value 1MΩ  [RESC1005L(0402)]  (hidden comment: RES-1MΩ-1/16W-100PPM-0402-1%)
R24  value 10kΩ  [RESQUAD1206]  (hidden comment: ACASA1002S1002P100)  (parts A,B,C,D of 4)
R25  value 10kΩ  [RESQUAD1206]  (hidden comment: ACASA1002S1002P100)  (parts A,B,C,D of 4)
R26  value 10kΩ  [RESQUAD1206]  (hidden comment: ACASA1002S1002P100)  (parts A,B,C,D of 4)
R27  value 10kΩ  [RESQUAD1206]  (hidden comment: ACASA1002S1002P100)  (parts A,B,C,D of 4)
R28  value 10kΩ  [RESQUAD1206]  (hidden comment: ACASA1002S1002P100)  (parts A,B,C,D of 4)
R29  value 10kΩ  [RESQUAD1206]  (hidden comment: ACASA1002S1002P100)  (parts A,B,C,D of 4)
R30  value 10kΩ  [RESQUAD1206]  (hidden comment: ACASA1002S1002P100)  (parts A,B,C,D of 4)
R31  value 10kΩ  [RESQUAD1206]  (hidden comment: ACASA1002S1002P100)  (parts A,B,C,D of 4)
R35  value 1MΩ  [RESC1005L(0402)]  (hidden comment: RES-1MΩ-1/16W-100PPM-0402-1%)
R37  value 1MΩ  [RESC1005L(0402)]  (hidden comment: RES-1MΩ-1/16W-100PPM-0402-1%)
R38  value 1MΩ  [RESC1005L(0402)]  (hidden comment: RES-1MΩ-1/16W-100PPM-0402-1%)
R39  value 1MΩ  [RESC1005L(0402)]  (hidden comment: RES-1MΩ-1/16W-100PPM-0402-1%)
R40  value 1MΩ  [RESC1005L(0402)]  (hidden comment: RES-1MΩ-1/16W-100PPM-0402-1%)
R71  value 1MΩ  [RESC1005L(0402)]  (hidden comment: RES-1MΩ-1/16W-100PPM-0402-1%)
R72  value 1MΩ  [RESC1005L(0402)]  (hidden comment: RES-1MΩ-1/16W-100PPM-0402-1%)
R73  value 1MΩ  [RESC1005L(0402)]  (hidden comment: RES-1MΩ-1/16W-100PPM-0402-1%)
R74  value 1MΩ  [RESC1005L(0402)]  (hidden comment: RES-1MΩ-1/16W-100PPM-0402-1%)
R75  value 1MΩ  [RESC1005L(0402)]  (hidden comment: RES-1MΩ-1/16W-100PPM-0402-1%)
R76  value 1MΩ  [RESC1005L(0402)]  (hidden comment: RES-1MΩ-1/16W-100PPM-0402-1%)
R77  value 1MΩ  [RESC1005L(0402)]  (hidden comment: RES-1MΩ-1/16W-100PPM-0402-1%)
R78  value 1MΩ  [RESC1005L(0402)]  (hidden comment: RES-1MΩ-1/16W-100PPM-0402-1%)
R79  value 1MΩ  [RESC1005L(0402)]  (hidden comment: RES-1MΩ-1/16W-100PPM-0402-1%)
R80  value 1.6Ω  [RESC1005L(0402)]  (hidden comment: RES-1.6Ω-1/16WW-200PPM-0402-5%)
R81  value 100kΩ  [RESC1005L(0402)]  (hidden comment: RES-100KΩ-1/16W-100PPM-0402-1%)
TP106  5001  [5001]  (value not drawn)
TP107  5001  [5001]  (value not drawn)
TP108  5001  [5001]  (value not drawn)
TP109  5001  [5001]  (value not drawn)
TP110  5001  [5001]  (value not drawn)
TP111  5001  [5001]  (value not drawn)
TP112  5001  [5001]  (value not drawn)
TP113  5001  [5001]  (value not drawn)
TP114  5001  [5001]  (value not drawn)
TP115  5001  [5001]  (value not drawn)
TP116  5001  [5001]  (value not drawn)
TP117  5001  [5001]  (value not drawn)
TP118  5001  [5001]  (value not drawn)
TP119  5001  [5001]  (value not drawn)
TP120  5001  [5001]  (value not drawn)
TP121  5001  [5001]  (value not drawn)
U3  THS4551IDGKT  [TSOP65P490-8AL]  (parts A,B of 2)
U4  THS4551IDGKT  [TSOP65P490-8AL]  (parts A,B of 2)
U5  THS4551IDGKT  [TSOP65P490-8AL]  (parts A,B of 2)
U6  THS4551IDGKT  [TSOP65P490-8AL]  (parts A,B of 2)
U7  THS4551IDGKT  [TSOP65P490-8AL]  (parts A,B of 2)
U8  THS4551IDGKT  [TSOP65P490-8AL]  (parts A,B of 2)
U9  THS4551IDGKT  [TSOP65P490-8AL]  (parts A,B of 2)
U10  THS4551IDGKT  [TSOP65P490-8AL]  (parts A,B of 2)
U14  NCS325SN2T1G  [SOT23-5AL]  (parts A,B of 2)

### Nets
5V2: C18.2 C19.2 C21.2 C22.2 C28.2 C29.2 C31.2 C32.2 C38.2 C39.2 C41.2 C42.2 C46.2 C47.2 C51.2 C52.2 C77.2 C79.2 JX3.10(5.2V) JX3.11(5.2V) JX3.13(5.2V) JX3.14(5.2V) JX3.16(5.2V) JX3.17(5.2V) JX3.44(5.2V) JX3.45(5.2V) JX3.47(5.2V) JX3.48(5.2V) JX3.50(5.2V) JX3.51(5.2V) U3.3(Vs+) U3.7(~{PD}) U4.3(Vs+) U4.7(~{PD}) U5.3(Vs+) U5.7(~{PD}) U6.3(Vs+) U6.7(~{PD}) U7.3(Vs+) U7.7(~{PD}) U8.3(Vs+) U8.7(~{PD}) U9.3(Vs+) U9.7(~{PD}) U10.3(Vs+) U10.7(~{PD}) U14.5(VDD)
GND: C18.1 C19.1 C20.1 C21.1 C22.1 C25.1 C28.1 C29.1 C30.1 C31.1 C32.1 C33.1 C38.1 C39.1 C40.1 C41.1 C42.1 C43.1 C46.1 C47.1 C50.1 C51.1 C52.1 C53.1 C77.1 C79.1 C80.1 C81.1 JX3.1(GND) JX3.4(GND) JX3.9(GND) JX3.12(GND) JX3.15(GND) JX3.18(GND) JX3.21(GND) JX3.24(GND) JX3.27(GND) JX3.30(GND) JX3.31(GND) JX3.34(GND) JX3.37(GND) JX3.40(GND) JX3.43(GND) JX3.46(GND) JX3.49(GND) JX3.52(GND) JX3.57(GND) JX3.60(GND) P1.1 P3.1 P5.1 P7.1 R3.1 R4.1 R35.1 R37.1 R38.1 R39.1 R40.1 R71.1 R72.1 R73.1 R74.1 R75.1 R76.1 R77.1 R78.1 R79.1 U3.6(Vs-) U4.6(Vs-) U5.6(Vs-) U6.6(Vs-) U7.6(Vs-) U8.6(Vs-) U9.6(Vs-) U10.6(Vs-) U14.2(VSS)
2V5REFBUF: C20.2 C25.2 C30.2 C33.2 C40.2 C43.2 C50.2 C53.2 C81.2 R80.2 U3.2(Vocm) U4.2(Vocm) U5.2(Vocm) U6.2(Vocm) U7.2(Vocm) U8.2(Vocm) U9.2(Vocm) U10.2(Vocm)
2V5REFOUT: R81.1
ADC0_N: P7.2 R24.3 R76.2
ADC0_P: P7.3 R24.2 R77.2
ADC1_N: P7.4 R26.3 R72.2
ADC1_P: P7.5 R26.2 R73.2
ADC2_N: P5.2 R28.3 R38.2
ADC2_P: P5.3 R28.2 R39.2
ADC3_N: P5.4 R3.2 R30.3
ADC3_P: P5.5 R4.2 R30.2
ADC4_N: P3.2 R25.3 R78.2
ADC4_P: P3.3 R25.2 R79.2
ADC5_N: P3.4 R27.3 R74.2
ADC5_P: P3.5 R27.2 R75.2
ADC6_N: P1.2 R29.3 R40.2
ADC6_P: P1.3 R29.2 R71.2
ADC7_N: P1.4 R31.3 R35.2
ADC7_P: P1.5 R31.2 R37.2
AIN0_N: C16.2 JX3.29(AIN_0N) R24.1 TP106.1(TP) U3.5(-)
AIN0_P: C23.2 JX3.28(AIN_0P) R24.4 TP108.1(TP) U3.4(+)
AIN1_N: C26.2 JX3.26(AIN_1N) R26.1 TP110.1(TP) U5.5(-)
AIN1_P: C34.2 JX3.25(AIN_1P) R26.4 TP112.1(TP) U5.4(+)
AIN2_N: C36.2 JX3.23(AIN_2N) R28.1 TP114.1(TP) U7.5(-)
AIN2_P: C44.2 JX3.22(AIN_2P) R28.4 TP116.1(TP) U7.4(+)
AIN3_N: C48.2 JX3.20(AIN_3N) R30.1 TP118.1(TP) U9.5(-)
AIN3_P: C54.2 JX3.19(AIN_3P) R30.4 TP120.1(TP) U9.4(+)
AIN4_N: C17.2 JX3.32(AIN_4N) R25.1 TP107.1(TP) U4.5(-)
AIN4_P: C24.2 JX3.33(AIN_4P) R25.4 TP109.1(TP) U4.4(+)
AIN5_N: C27.2 JX3.35(AIN_5N) R27.1 TP111.1(TP) U6.5(-)
AIN5_P: C35.2 JX3.36(AIN_5P) R27.4 TP113.1(TP) U6.4(+)
AIN6_N: C37.2 JX3.38(AIN_6N) R29.1 TP115.1(TP) U8.5(-)
AIN6_P: C45.2 JX3.39(AIN_6P) R29.4 TP117.1(TP) U8.4(+)
AIN7_N: C49.2 JX3.41(AIN_7N) R31.1 TP119.1(TP) U10.5(-)
AIN7_P: C55.2 JX3.42(AIN_7P) R31.4 TP121.1(TP) U10.4(+)
NetC16_1: C16.1 R24.7 R24.8 U3.8(+)
NetC17_1: C17.1 R25.7 R25.8 U4.8(+)
NetC23_1: C23.1 R24.5 R24.6 U3.1(-)
NetC24_1: C24.1 R25.5 R25.6 U4.1(-)
NetC26_1: C26.1 R26.7 R26.8 U5.8(+)
NetC27_1: C27.1 R27.7 R27.8 U6.8(+)
NetC34_1: C34.1 R26.5 R26.6 U5.1(-)
NetC35_1: C35.1 R27.5 R27.6 U6.1(-)
NetC36_1: C36.1 R28.7 R28.8 U7.8(+)
NetC37_1: C37.1 R29.7 R29.8 U8.8(+)
NetC44_1: C44.1 R28.5 R28.6 U7.1(-)
NetC45_1: C45.1 R29.5 R29.6 U8.1(-)
NetC48_1: C48.1 R30.7 R30.8 U9.8(+)
NetC49_1: C49.1 R31.7 R31.8 U10.8(+)
NetC54_1: C54.1 R30.5 R30.6 U9.1(-)
NetC55_1: C55.1 R31.5 R31.6 U10.1(-)
NetC80_2: C80.2 R81.2 U14.3(IN+)
NetR80_1: R80.1 U14.1(OUT) U14.4(IN-)

Not connected (* = marked no-connect by the designer): JX3 2(N/A)* 3(N/A)* 5(N/A)* 6(N/A)* 7(N/A)* 8(N/A)* 53(N/A)* 54(N/A)* 55(N/A)* 56(N/A)* 58(N/A)* 59(N/A)*

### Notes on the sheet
- Analog differential inputs
- The input range is 0 to 5V for all signals (_P and _N). This is why, in differential mode, the range is ± 5V.
- 1MΩ input resistors are not necessary in most applications. On this evaluation board, these resistors allow the inputs to be polarized when there is no connection to the analog inputs.
- Resistor networks allow superior gain accuracy of the driver stage.
- User can implement lower resistors values, such as 1kΩ instead of 10kΩ. This reduces noise but also reduces the impedance of the analog inputs.
- Full-differential amplifiers are used for larger common-mode input voltage range and lower total input offset voltage.
- Analog Inputs
- (near P5) ADC2 & ADC3
- (near P1) ADC6 & ADC7
- (near P7) ADC0 & ADC1
- (near P3) ADC4 & ADC5
- 2.5VRef buffering for common mode

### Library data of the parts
C16 C17 C23 C24 C26 C27 C34-C37 C44 C45 C48 C49 C54 C55 = CMP-004-000007-13: CAP CER 12PF 50V C0G 0402 5% (Generic Imperix Component)
C18 C21 C28 C31 C38 C41 C46 C51 C77 = CMP-004-000006-18: as C57 on sheet Power
C19 C22 C29 C32 C39 C42 C47 C52 C79 = CMP-055-000003-7: as C56 on sheet Power
C20 C25 C30 C33 C40 C43 C50 C53 C80 C81 = CMP-004-000008-13: as C72 on sheet Power
JX3 = CMP-070-000037-3: JX3 for BBoard; Number of Contacts: 60; Pitch: 0.5mm; Gender: Female; Mated Stacking Heights: 5mm
P1 P3 P5 P7 = CMP-003-000046-13: as P9 on sheet DAC
R3 R4 R35 R37-R40 R71-R79 = CMP-00160-1: RES SMD 1MΩ 1/16W 100PPM 0402 1% (Generic Imperix Component); Temperature Coefficient: 100ppm/°C
R24-R31 = CMP-017-000003-7: 10k Ohm ±0.1% 100mW Power Per Element Isolated 4 Resistor Network/Array ±25ppm/°C 1206 (3216 Metric), Convex, Long Side Terminals; Number of Resistors: 4; Tolerance Relative: 0.05%
R80 = CMP-004-000018-3: as R34 on sheet Power
R81 = CMP-009-000006-6: RES SMD 100KΩ 1/16W 100PPM 0402 1% (Generic Imperix Component); Temperature Coefficient: 100ppm/°C
TP106-TP121 = CMP-049-000000-14: as TP101 on sheet DAC
U3-U10 = CMP-011-000002-8: Low Noise, Precision, 150MHz, Fully Differential Amplifier 8-TSOP -40 to 125; Bandwidth: 135MHz; Slew Rate: 220V/µs; Operating Supply Current: 1.35mA; Number of Circuits: 1; Input Offset Voltage (Vos): 50uV; Input Bias Current: 1uA
U14 = CMP-00165-2: Single Operational Amplifier, 50 µV Offset, 0.25 µV/°C, Zero-Drift Precision, Low Power; Output Current per Channel: 5mA; Input Offset Voltage (Vos): 14uV; Input Bias Current: 50pA; Slew Rate: 0.16V/µs; Gain Bandwidth Product: 350kHz; Operating Supply Current: 21uA; Number of Circuits: 1

## Sheet BBoard-JX1.SchDoc: Eval Board -  BBoard JX1 connector (Ethernet , CAN bus)
size A3; ApprovedBy: Nicolas Cherix; Author: O. Guinnard; Organization: imperix Ltd; Address1: Rue de l'Industrie 10; Address2: 1950 Sion; Address3: Switzerland; Address4: +41 27 552 06 60; Revision: C1; SheetNumber: 4; SheetTotal: 6
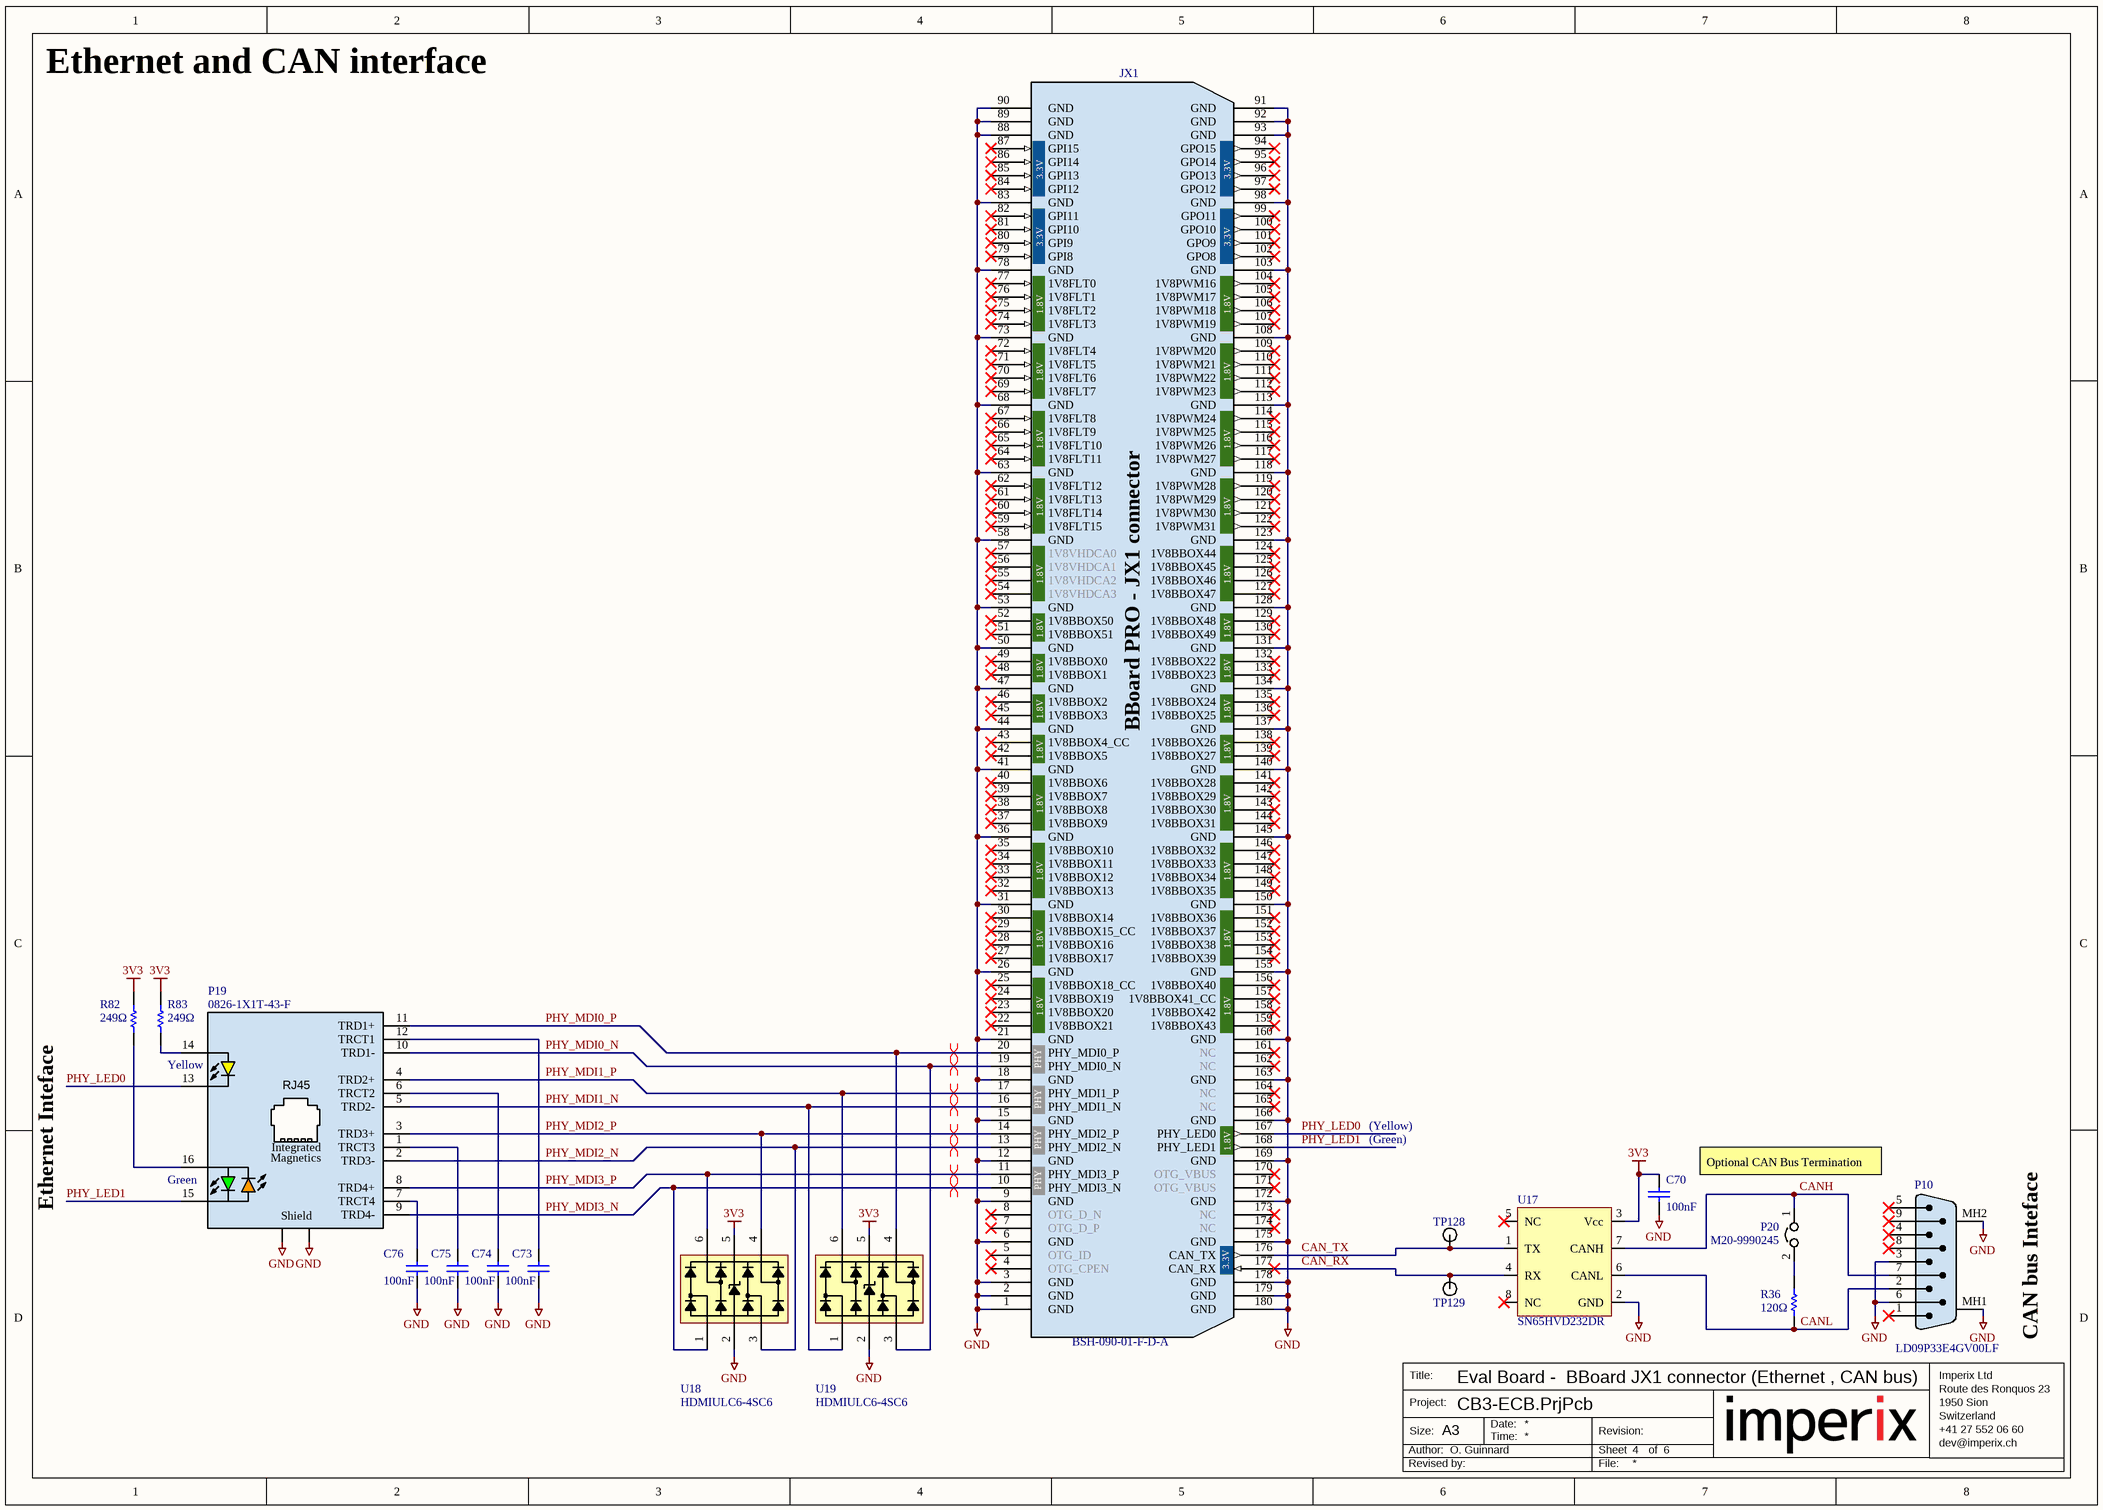
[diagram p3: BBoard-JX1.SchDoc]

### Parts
C70  value 100nF  [CAPC1005L(0402)]  (hidden comment: CAP-100NF-25V-X7R-0402-10%)
C73  value 100nF  [CAPC1005L(0402)]  (hidden comment: CAP-100NF-25V-X7R-0402-10%)
C74  value 100nF  [CAPC1005L(0402)]  (hidden comment: CAP-100NF-25V-X7R-0402-10%)
C75  value 100nF  [CAPC1005L(0402)]  (hidden comment: CAP-100NF-25V-X7R-0402-10%)
C76  value 100nF  [CAPC1005L(0402)]  (hidden comment: CAP-100NF-25V-X7R-0402-10%)
JX1  BSH-090-01-F-D-A  [BSH-090-01-F-D-A]
P10  LD09P33E4GV00LF  [LD09P33E4GV00LF]
P19  0826-1X1T-43-F  [BEL_0826-1X1T-43-F]
P20  M20-9990245  [M20-9990245]
R36  value 120Ω  [RESC1608L(0603)]  (hidden comment: RES-120Ω-1/8W-50PPM-0603-1%)
R82  value 249Ω  [RESC1005L(0402)]  (hidden comment: RES-249Ω-1/16W-100PPM-0402-1%)
R83  value 249Ω  [RESC1005L(0402)]  (hidden comment: RES-249Ω-1/16W-100PPM-0402-1%)
TP128  5001  [5001]  (value not drawn)
TP129  5001  [5001]  (value not drawn)
U17  SN65HVD232DR  [SOIC127P600-8AL]
U18  HDMIULC6-4SC6  [SOT23-6N]
U19  HDMIULC6-4SC6  [SOT23-6N]

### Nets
3V3: C70.2 R82.2 R83.2 U17.3(Vcc) U18.5 U19.5
GND: C70.1 C73.1 C74.1 C75.1 C76.1 JX1.1(GND) JX1.2(GND) JX1.3(GND) JX1.6(GND) JX1.9(GND) JX1.12(GND) JX1.15(GND) JX1.18(GND) JX1.21(GND) JX1.26(GND) JX1.31(GND) JX1.36(GND) JX1.41(GND) JX1.44(GND) JX1.47(GND) JX1.50(GND) JX1.53(GND) JX1.58(GND) JX1.63(GND) JX1.68(GND) JX1.73(GND) JX1.78(GND) JX1.83(GND) JX1.88(GND) JX1.89(GND) JX1.90(GND) JX1.91(GND) JX1.92(GND) JX1.93(GND) JX1.98(GND) JX1.103(GND) JX1.108(GND) JX1.113(GND) JX1.118(GND) JX1.123(GND) JX1.128(GND) JX1.131(GND) JX1.134(GND) JX1.137(GND) JX1.140(GND) JX1.145(GND) JX1.150(GND) JX1.155(GND) JX1.160(GND) JX1.163(GND) JX1.166(GND) JX1.169(GND) JX1.172(GND) JX1.175(GND) JX1.178(GND) JX1.179(GND) JX1.180(GND) P10.3 P10.6 P10.MH1(SH) P10.MH2(SH) P19.S1(SHIELD) P19.S2(SHIELD) U17.2(GND) U18.2 U19.2
CAN_RX: JX1.177(CAN_RX) TP129.1(TP) U17.4(RX)
CAN_TX: JX1.176(CAN_TX) TP128.1(TP) U17.1(TX)
CANH: P10.7 P20.1 U17.7(CANH)
CANL: P10.2 R36.1 U17.6(CANL)
PHY_LED0: JX1.167(PHY_LED0) P19.13
PHY_LED1: JX1.168(PHY_LED1) P19.15
PHY_MDI0_N: JX1.19(PHY_MDI0_N) P19.10(TRD1-) U19.3
PHY_MDI0_P: JX1.20(PHY_MDI0_P) P19.11(TRD1+) U19.4
PHY_MDI1_N: JX1.16(PHY_MDI1_N) P19.5(TRD2-) U19.1
PHY_MDI1_P: JX1.17(PHY_MDI1_P) P19.4(TRD2+) U19.6
PHY_MDI2_N: JX1.13(PHY_MDI2_N) P19.2(TRD3-) U18.3
PHY_MDI2_P: JX1.14(PHY_MDI2_P) P19.3(TRD3+) U18.4
PHY_MDI3_N: JX1.10(PHY_MDI3_N) P19.9(TRD4-) U18.1
PHY_MDI3_P: JX1.11(PHY_MDI3_P) P19.8(TRD4+) U18.6
NetC73_2: C73.2 P19.12(TRCT1)
NetC74_2: C74.2 P19.6(TRCT2)
NetC75_2: C75.2 P19.1(TRCT3)
NetC76_2: C76.2 P19.7(TRCT4)
NetP19_14: P19.14 R83.1
NetP19_16: P19.16 R82.1
NetP20_2: P20.2 R36.2

Not connected (* = marked no-connect by the designer): JX1 4(OTG_CPEN)* 5(OTG_ID)* 7(OTG_D_P)* 8(OTG_D_N)* 22(1V8BBOX21)* 23(1V8BBOX20)* 24(1V8BBOX19)* 25(1V8BBOX18_CC)* 27(1V8BBOX17)* 28(1V8BBOX16)* 29(1V8BBOX15_CC)* 30(1V8BBOX14)* 32(1V8BBOX13)* 33(1V8BBOX12)* 34(1V8BBOX11)* 35(1V8BBOX10)* 37(1V8BBOX9)* 38(1V8BBOX8)* 39(1V8BBOX7)* 40(1V8BBOX6)* 42(1V8BBOX5)* 43(1V8BBOX4_CC)* 45(1V8BBOX3)* 46(1V8BBOX2)* 48(1V8BBOX1)* 49(1V8BBOX0)* 51(1V8BBOX51)* 52(1V8BBOX50)* 54(1V8VHDCA3)* 55(1V8VHDCA2)* 56(1V8VHDCA1)* 57(1V8VHDCA0)* 59(1V8FLT15)* 60(1V8FLT14)* 61(1V8FLT13)* 62(1V8FLT12)* 64(1V8FLT11)* 65(1V8FLT10)* 66(1V8FLT9)* 67(1V8FLT8)* 69(1V8FLT7)* 70(1V8FLT6)* 71(1V8FLT5)* 72(1V8FLT4)* 74(1V8FLT3)* 75(1V8FLT2)* 76(1V8FLT1)* 77(1V8FLT0)* 79(GPI8)* 80(GPI9)* 81(GPI10)* 82(GPI11)* 84(GPI12)* 85(GPI13)* 86(GPI14)* 87(GPI15)* 94(GPO15)* 95(GPO14)* 96(GPO13)* 97(GPO12)* 99(GPO11)* 100(GPO10)* 101(GPO9)* 102(GPO8)* 104(1V8PWM16)* 105(1V8PWM17)* 106(1V8PWM18)* 107(1V8PWM19)* 109(1V8PWM20)* 110(1V8PWM21)* 111(1V8PWM22)* 112(1V8PWM23)* 114(1V8PWM24)* 115(1V8PWM25)* 116(1V8PWM26)* 117(1V8PWM27)* 119(1V8PWM28)* 120(1V8PWM29)* 121(1V8PWM30)* 122(1V8PWM31)* 124(1V8BBOX44)* 125(1V8BBOX45)* 126(1V8BBOX46)* 127(1V8BBOX47)* 129(1V8BBOX48)* 130(1V8BBOX49)* 132(1V8BBOX22)* 133(1V8BBOX23)* 135(1V8BBOX24)* 136(1V8BBOX25)* 138(1V8BBOX26)* 139(1V8BBOX27)* 141(1V8BBOX28)* 142(1V8BBOX29)* 143(1V8BBOX30)* 144(1V8BBOX31)* 146(1V8BBOX32)* 147(1V8BBOX33)* 148(1V8BBOX34)* 149(1V8BBOX35)* 151(1V8BBOX36)* 152(1V8BBOX37)* 153(1V8BBOX38)* 154(1V8BBOX39)* 156(1V8BBOX40)* 157(1V8BBOX41_CC)* 158(1V8BBOX42)* 159(1V8BBOX43)* 161(NC)* 162(NC)* 164(NC)* 165(NC)* 170(OTG_VBUS)* 171(OTG_VBUS)* 173(NC)* 174(NC)*; P10 1* 4* 5* 8* 9*; U17 5(NC)* 8(NC)*

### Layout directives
differential pair: PHY_MDI0_N, PHY_MDI0_P, PHY_MDI1_N, PHY_MDI1_P, PHY_MDI2_N, PHY_MDI2_P, PHY_MDI3_N, PHY_MDI3_P

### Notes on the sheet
- Ethernet and CAN interface
- Ethernet Inteface
- (near P19) Yellow
- (Yellow)
- (near P19) Green
- (Green)
- Optional CAN Bus Termination
- CAN bus Inteface

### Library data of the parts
C70 C73-C76 = CMP-004-000006-18: as C57 on sheet Power
JX1 = CMP-070-000035-8: JX1 for BBoard; Max Current Rating: 1.25A; Gender: Female; Number of Contacts: 180; Pitch: 0.5mm; Mated Stacking Heights: 5mm; Max Voltage Rating (AC): 125V
P10 = CMP-255-000000-9: Conn D-Subminiature PIN 9 POS 2.74mm Solder RA Thru-Hole 9 Terminal 1 Port; Manufacturer_Name: Amphenol Communications Solutions; Connector Type: D-Sub,Plug; Voltage Rating: 250V; Geometry.Height: 12.96mm; Number of Positions: 9; Current Rating: 5A
P19 = CMP-265-000000-4: Conn Modular Jack RCP 12 POS 2.03mm Solder RA Thru-Hole 16 Terminal 1 Port Tray; Number of Ports: 1; Direction: Up; Number of Positions Loaded: 12; Shielding: Shielded; Number of Cores per Jack: 8; Gender: Female; Connector Type: RJ45
P20 = CMP-070-000025-6: Connector Header Through Hole 2 position 0.100" (2.54mm); Max Current Rating: 3A; Voltage Rating (AC): 750V; Number of Contacts: 2; Contact Resistance: 25mR; Gender: Male; Insulation Resistance: 10GR; Mating Cycles: 300; Mated Stacking Heights: 16.54mm; Voltage: 50V
R36 = CMP-006-000016-3: RES SMD 120Ω 1/8W 50PPM 0603 1% (Generic Imperix Component); Temperature Coefficient: 50ppm/°C
R82 R83 = CMP-132-000003-2: as R32 on sheet Power
TP128 TP129 = CMP-049-000000-14: as TP101 on sheet DAC
U17 = CMP-00049-3: Texas Instruments - SN65HVD232DR - Can Transceiver, 1MBPS, 1/1, 3.3V, SOIC-8, Full Reel; Number of Receive Buffers: 1; Min Supply Voltage: 3V; Max Supply Voltage: 3.6V; Simplex/Duplex: Half Duplex; Supply Current: 17mA; Receiver Hysteresis: 100mV
U18 U19 = CMP-050-000000-12: HDMIULC6 Series 4 Channel 6 V Bi-Directional ESD Protection - SOT-23-6; Breakdown Voltage: 6V; Clamping Voltage-Max: 17V; Direction: Unidirectional,Bidirectional; ESD Protection: Yes; Leakage Current: 500nA; Number of Bidirectional Channels: 4; Number of Elements: 1; Operating Supply Voltage: 5V; Peak Pulse Current: 5A; Polarity: Bidirectional,Unidirectional; Test Current: 1mA; Value: 1pF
